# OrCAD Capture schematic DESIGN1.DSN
size A4; title: TEST LAYOUT SCHEMATIC; note: flinck01
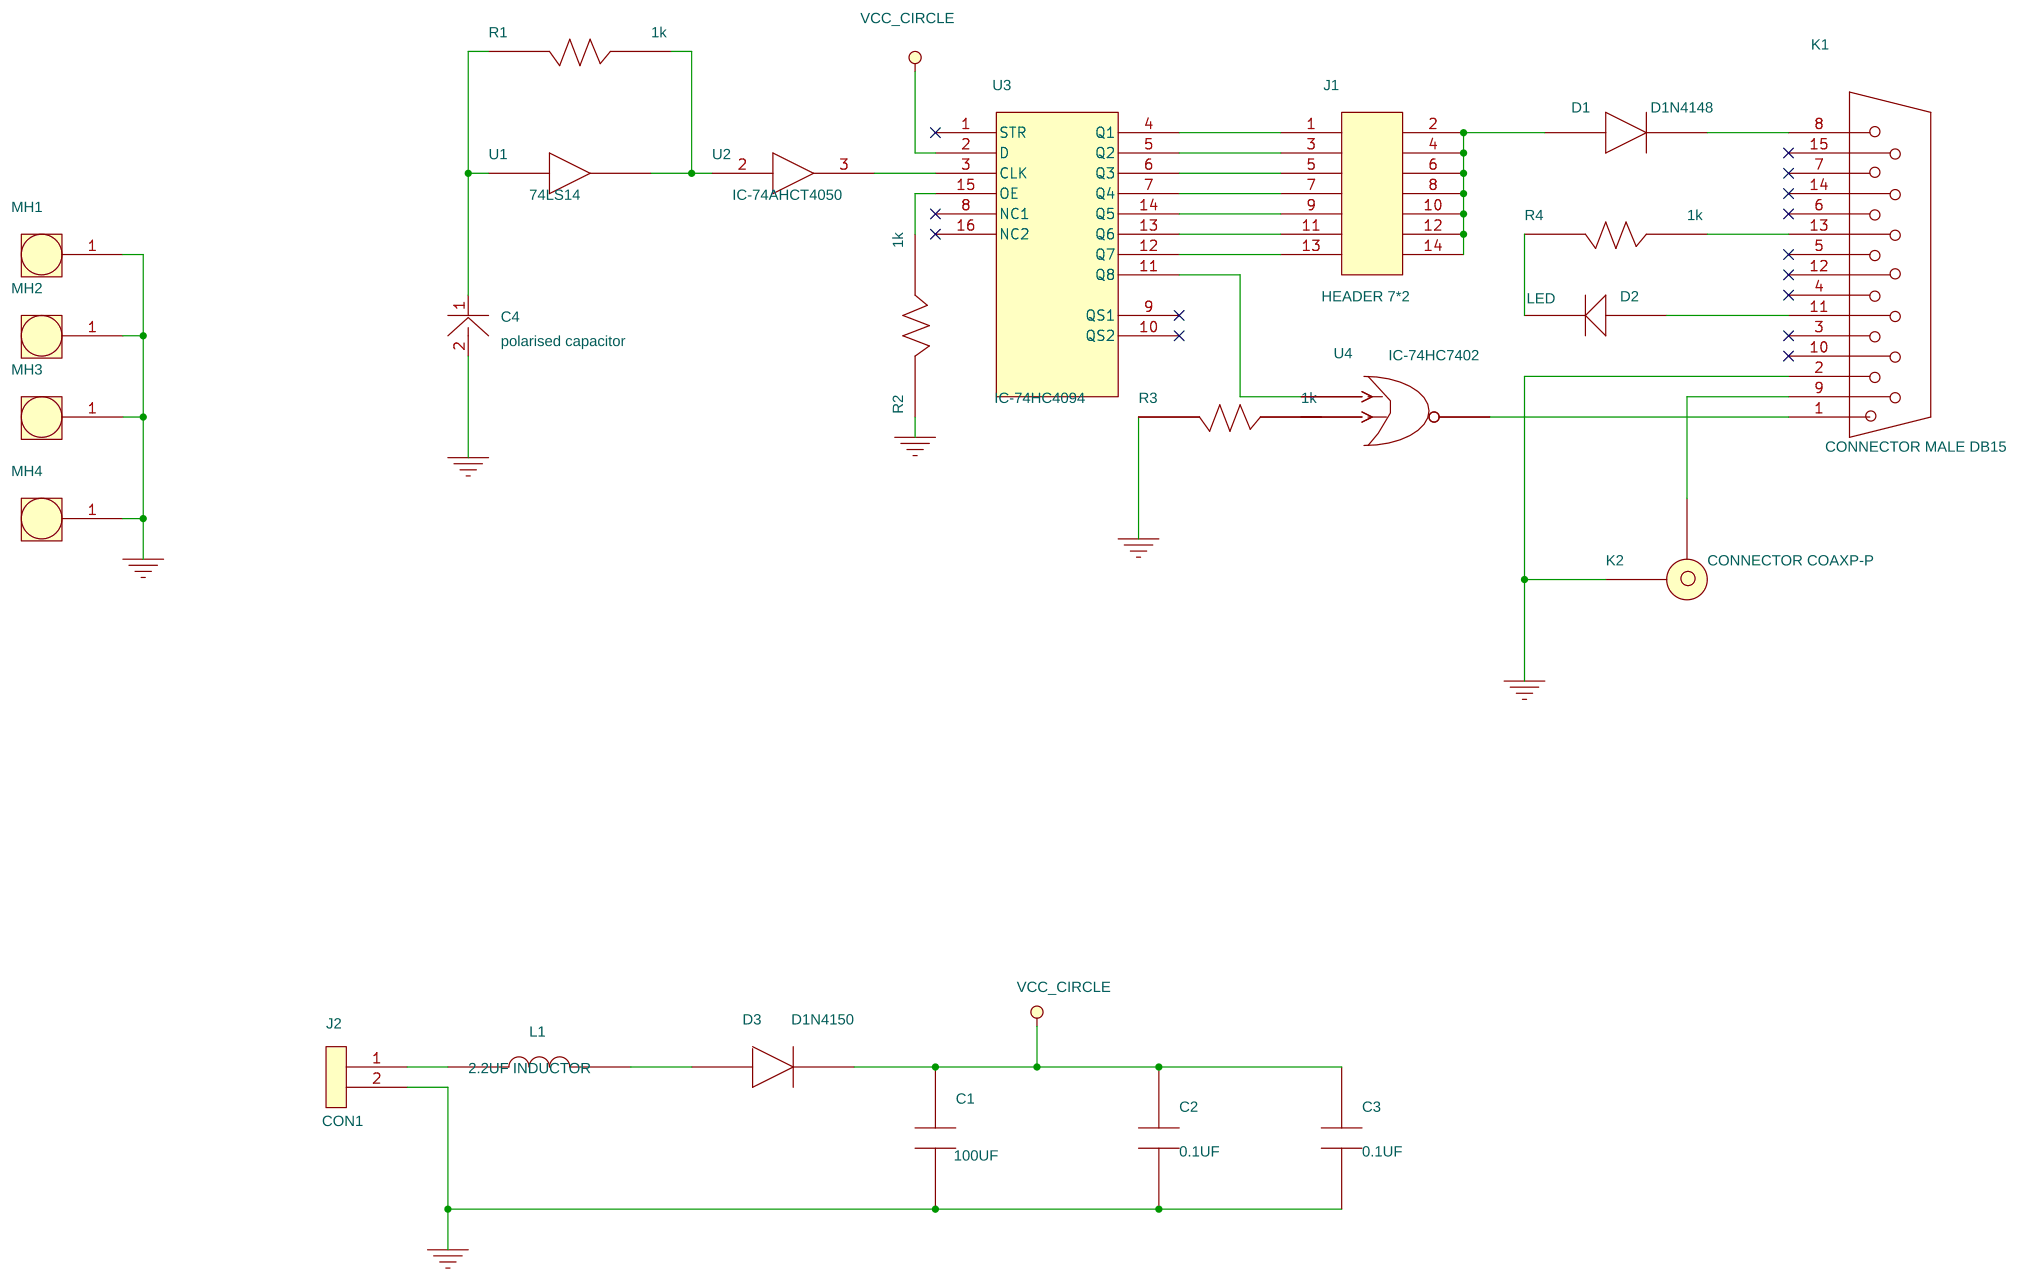
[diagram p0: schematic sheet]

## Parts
C1  100UF  [C]
C2  0.1UF  [C]
C3  0.1UF  [C]
C4  polarised capacitor  [c4]
D1  D1N4148  [D1]
D2  LED  [LED]
D3  D1N4150  [D2]
J1  HEADER 7*2  [J1]
J2  CON1  [COAXP-P]
K1  CONNECTOR MALE DB15  [K1]
K2  CONNECTOR COAXP-P  [K2]
L1  2.2UF INDUCTOR  [L1]
MH1  MH  [MH]
MH2  MH  [MH]
MH3  MH  [MH]
MH4  MH  [MH]
R1  1k  [R]
R2  1k  [R]
R3  1k  [R]
R4  1k  [R]
U1  74LS14  [U1]
U2  IC-74AHCT4050  [U2]
U3  IC-74HC4094  [U3]
U4  IC-74HC7402  [U4]

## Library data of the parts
C1 = 100UF_2
C2 C3 = 0_1.1UF
C4 = polarised_capacitor
D1 = D1N4148_1
D2 = LED_2
D3 = D1N4150_1
J1 = HEADER_7*2_1
J2 = CON1_3
K1 = CONNECTOR_MALE_DB15
K2 = CONNECTOR_COAXP-P_1
L1 = 2_2.2UF_INDUCTOR
MH1-MH4 = MH
R1-R4 = 1k_0
U1 = IC-74AHCT4050_2
U2 = IC-74AHCT4050_4
U3 = IC-74HC4094
U4 = IC-74HC7402_1

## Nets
GND_POWER: C1.1 C2.1 C3.1 C4.2 J2.2 K1.2 K2.1 MH1.1 MH2.1 MH3.1 MH4.1 R2.1 R3.1
VCC_CIRCLE: C1.2 C2.2 C3.2 D3.2 U3.2(D)
N01450: C4.1 R1.1 U1.1
N01454: R1.2 U1.2 U2.2
N01555: J1.1 U3.4(Q1)
N01559: J1.3 U3.5(Q2)
N01563: J1.5 U3.6(Q3)
N01567: J1.7 U3.7(Q4)
N01571: J1.9 U3.14(Q5)
N01575: J1.11 U3.13(Q6)
N01579: J1.13 U3.12(Q7)
N01592: U3.11(Q8) U4.1
N01607: R3.2 U4.2
N01687: D1.2 K1.8
N01709: D2.2 K1.11
N01734: K1.9 K2.2
N04292: K1.13 R4.2
N07299: K1.1 U4.3
N07457: R2.2 U3.15(OE)
N07591: U2.3 U3.3(CLK)
N11029: J2.1 L1.1
N11174: D3.1 L1.2
N15731: D2.1 R4.1
N16100: D1.1 J1.2 J1.4 J1.6 J1.8 J1.10 J1.12 J1.14

Not connected (* = marked no-connect by the designer): K1 3* 4* 5* 6* 7* 10* 12* 14* 15*; U3 1(STR)* 8(NC1)* 9(QS1)* 10(QS2)* 16(NC2)*
